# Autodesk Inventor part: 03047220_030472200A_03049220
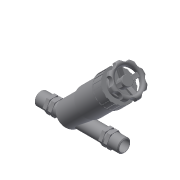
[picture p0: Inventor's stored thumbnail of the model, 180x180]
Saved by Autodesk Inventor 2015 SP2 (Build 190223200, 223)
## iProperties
Created: 2017-05
Part Number: 03047220_030472200A_03049220
Material: Generic
Description: PLASSON ANGLE SEAT VALVE 2"-2"
Document SubType Name: Modeling
Designer: KIM
Density: 1 g/cm^3
Appearance: Default
Author: KIM
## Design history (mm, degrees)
derived "03049.ipt"
feature "Solid1::03049.ipt"
tag "TaggingFeature1"
body "Solid1"
other parameters: "d0" = 254, "d1" = 59.614, "d2" = 65, "d3" = 47.6912, "d4" = 26, "d5" = 26, "d6" = 25.4, "d8" = 2.54, "d12" = 0, "d14" = -12.7, "d15" = 5.08, "d16" = 0, "d17" = 73.062, "d18" = 8.856, "d19" = 243.54, "d20" = 83.025, "d21" = 135 deg, "d22" = 94.095, "d23" = 44.28, "d24" = 105.165, "d25" = 26.568, "d26" = 90 deg, "d27" = 77.49, "d28" = 70 deg, "d29" = 33.21, "d30" = 26.568, "d31" = 33.21, "d32" = 110.7, "d33" = 77.49, "d34" = 135 deg, "d35" = 2, "d36" = 221.4, "d39" = 88.9, "d40" = 2.46, "d41" = 1, "d42" = 0.5, "d43" = 7.38, "d44" = 7.38, "d46" = 0, "d48" = 360 deg, "d50" = 1.23, "d51" = 1.23, "d53" = 360 deg, "d69" = 94.095, "d70" = 7.38, "d71" = 7.38, "d72" = 14.76, "d74" = 0, "d75" = 1.23, "d77" = 360 deg, "d80" = 102.01005, "d81" = 9.84, "d82" = 4.92, "d83" = 39.852, "d84" = 0, "d86" = 360 deg, "d88" = 2.46, "d91" = 246, "H_" = 254, "R_" = 59.614, "E_" = 65, "l_2" = 26, "A_" = 246, "d13" = 25.4, "d67" = 110.7, "d68" = 77.49, "d79" = 105.165
